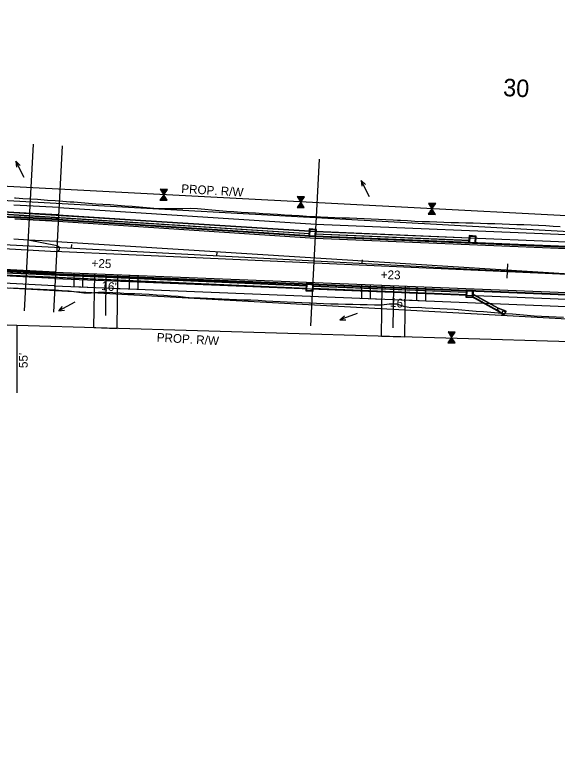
# Model space of a CAD drawing. Extents: x 670017 to 673226, y 705371 to 707498.
# Drawn here: x 672160 to 672533, y 706170 to 706677 of the extents above; entities that cross this region are included whole.
import ezdxf

# ---------------------------------------------------------------- set-up
doc = ezdxf.new("R2010")
doc.units = 0
for name, color, linetype in [('EL L 264', 7, 'Continuous'), ('EL R 264', 7, 'Continuous'), ('R_Drainage Flow Lines', 7, 'Continuous'), ('R_Drainage Stage 1', 7, 'Continuous'), ('R_Drainage Stage 2', 7, 'Continuous'), ('R_Drainage Stage 2A', 7, 'Continuous'), ('R_Drive Annot Stage 2', 7, 'Continuous'), ('R_Drive Stage 2', 7, 'Continuous'), ('R_Fence', 7, 'Continuous'), ('R_Horz Alg', 7, 'Continuous'), ('R_Horz Alg Station', 7, 'Continuous'), ('R_Horz Alg Station Annot', 7, 'Continuous'), ('R_No Plot', 7, 'Continuous'), ('R_No Plot FOC', 7, 'Continuous'), ('R_Proposed Const Limits', 7, 'Continuous'), ('R_Proposed Const Limits Stage 2', 7, 'Continuous'), ('R_Proposed Median', 7, 'Continuous'), ('R_Proposed Road', 7, 'Continuous'), ('R_Proposed Road Stage 2', 7, 'Continuous'), ('R_Proposed Sidewalk Stage 1', 7, 'Continuous'), ('R_Proposed Sidewalk Stage 2', 7, 'Continuous'), ('R_ROW', 7, 'Continuous'), ('R_ROW Annot', 7, 'Continuous'), ('R_Striping', 7, 'Continuous'), ('R_Water Annot', 7, 'Continuous'), ('S_EXIST_ROW', 7, 'Continuous')]:
    doc.layers.add(name, color=color, linetype=linetype)

# ---------------------------------------------------------------- blocks, each defined once
blk = doc.blocks.new('FLOW ARROW')
at = {"layer": 'R_Water Annot'}
for p, q in [((-12.57, 0), (0, 0)), ((0, 0), (-3.85, 1.4)), ((0, 0), (-3.85, -1.4))]:
    blk.add_line(p, q, dxfattribs=at)

msp = doc.modelspace()

# ---------------------------------------------------------------- linework, layer by layer
at = {"layer": 'EL L 264'}
for p, q in [((672160.34, 706537.01), (672189.95, 706535.46)), ((672160.34, 706537.01), (672189.95, 706535.46)), ((672189.95, 706535.46), (672366.78, 706523.88)), ((672189.95, 706535.46), (672366.78, 706523.88)), ((672366.78, 706523.88), (672574.61, 706515.27)), ((672366.78, 706523.88), (672574.61, 706515.27))]:
    msp.add_line(p, q, dxfattribs=at)
at = {"layer": 'EL R 264'}
for p, q in [((671935.55, 706513.76), (672188.31, 706500.5)), ((672187.89, 706500.52), (672563.37, 706485.4))]:
    msp.add_line(p, q, dxfattribs=at)
at = {"layer": 'R_Drainage Stage 1'}
for p, q in [((672362.93, 706526.71), (672152.34, 706540.08)), ((672362.94, 706526.88), (672152.35, 706540.24)), ((672363.02, 706528.38), (672152.43, 706541.74)), ((672363.03, 706528.54), (672152.44, 706541.91)), ((672472.91, 706523.74), (672367.01, 706528.17)), ((672472.92, 706523.9), (672367.02, 706528.33)), ((672472.84, 706522.24), (672366.93, 706526.67)), ((672472.83, 706522.07), (672366.93, 706526.5))]:
    msp.add_line(p, q, dxfattribs=at)
for points in [[(672367.34, 706524.88), (672367.6, 706529.87), (672362.61, 706530.13), (672362.35, 706525.14)], [(672366.87, 706525.4), (672367.08, 706529.4), (672363.08, 706529.6), (672362.87, 706525.61)], [(672477.24, 706520.28), (672477.5, 706525.27), (672472.51, 706525.53), (672472.25, 706520.54)], [(672476.77, 706520.8), (672476.98, 706524.8), (672472.98, 706525.01), (672472.77, 706521.01)]]:
    msp.add_lwpolyline(points, close=True, dxfattribs=at)
at = {"layer": 'R_Drainage Stage 2'}
for p, q in [((672360.96, 706489.14), (672125.16, 706499.41)), ((672360.97, 706489.3), (672125.17, 706499.57)), ((672361.05, 706490.8), (672125.25, 706501.07)), ((672361.05, 706490.97), (672125.26, 706501.24)), ((672470.88, 706484.87), (672364.96, 706489.13)), ((672470.88, 706484.7), (672364.96, 706488.97)), ((672470.95, 706486.37), (672365.04, 706490.63)), ((672470.95, 706486.53), (672365.05, 706490.8)), ((672474.79, 706483.46), (672491.71, 706474.13)), ((672491.79, 706474.27), (672474.83, 706483.62)), ((672474.9, 706485.3), (672492.51, 706475.59)), ((672492.59, 706475.73), (672474.91, 706485.48))]:
    msp.add_line(p, q, dxfattribs=at)
for points in [[(672360.64, 706492.59), (672360.38, 706487.6), (672365.37, 706487.34), (672365.63, 706492.33)], [(672361.11, 706492.07), (672360.9, 706488.07), (672364.9, 706487.86), (672365.11, 706491.86)], [(672470.31, 706483.14), (672475.31, 706482.94), (672475.52, 706487.93), (672470.52, 706488.14)], [(672470.83, 706483.62), (672474.83, 706483.46), (672474.99, 706487.45), (672471, 706487.62)]]:
    msp.add_lwpolyline(points, close=True, dxfattribs=at)
at = {"layer": 'R_Drainage Stage 2A'}
for p, q in [((672491.71, 706474.13), (672491.81, 706474.31)), ((672496.46, 706470.69), (672491.71, 706474.13)), ((672491.81, 706474.31), (672492.5, 706475.56)), ((672491.81, 706474.31), (672492.01, 706474.19)), ((672492.01, 706474.19), (672492.71, 706475.45)), ((672496.55, 706470.87), (672492.02, 706474.21)), ((672492.5, 706475.56), (672492.59, 706475.74)), ((672492.5, 706475.56), (672492.71, 706475.45)), ((672498.04, 706473.56), (672492.59, 706475.74)), ((672497.94, 706473.38), (672492.7, 706475.43)), ((672496.55, 706470.87), (672495.49, 706472.07)), ((672495.49, 706472.07), (672496.46, 706470.69)), ((672497.94, 706473.38), (672496.36, 706473.65)), ((672496.36, 706473.65), (672498.04, 706473.56)), ((672496.55, 706470.87), (672497.94, 706473.38)), ((672497.94, 706473.38), (672498.04, 706473.56)), ((672496.55, 706470.87), (672496.46, 706470.69))]:
    msp.add_line(p, q, dxfattribs=at)
msp.add_arc((672496.2, 706472.7), 0.957, 80.5096, 221.7347, dxfattribs=at)
at = {"layer": 'R_Drive Stage 2'}
for p, q in [((672201.14, 706490.48), (672201.27, 706499.98)), ((672207.14, 706490.22), (672207.27, 706499.74)), ((672214.76, 706462.29), (672215.26, 706498.99)), ((672230.75, 706461.81), (672231.25, 706498.77)), ((672239.12, 706489.05), (672239.25, 706498.45)), ((672245.12, 706488.71), (672245.25, 706498.21)), ((672398.78, 706482.52), (672398.9, 706491.8)), ((672404.77, 706482.28), (672404.9, 706491.58)), ((672201.14, 706490.48), (672215.13, 706489.91)), ((672231.13, 706489.27), (672245.12, 706488.71)), ((672412.42, 706456.46), (672412.9, 706491.29)), ((672428.42, 706455.99), (672428.89, 706490.71)), ((672436.76, 706480.99), (672436.89, 706490.42)), ((672442.76, 706480.75), (672442.89, 706490.2)), ((672398.78, 706482.52), (672412.77, 706481.95)), ((672428.76, 706481.31), (672442.76, 706480.75)), ((672214.76, 706462.29), (672230.75, 706461.81)), ((672412.42, 706456.46), (672428.42, 706455.99))]:
    msp.add_line(p, q, dxfattribs=at)
at = {"layer": 'R_Fence'}
for p, q in [((672260.8, 706557.48), (672260.53, 706557.22)), ((672261.51, 706557.46), (672260.8, 706556.79)), ((672262.21, 706557.43), (672261.07, 706556.36)), ((672262.92, 706557.41), (672261.34, 706555.92)), ((672263.63, 706557.39), (672261.61, 706555.49)), ((672264.33, 706557.37), (672261.88, 706555.06)), ((672263.23, 706552.9), (672260.15, 706549.99)), ((672263.5, 706552.46), (672260.86, 706549.97)), ((672262.96, 706553.33), (672261.59, 706552.04)), ((672265.04, 706557.35), (672262.15, 706554.63)), ((672264.54, 706556.19), (672262.42, 706554.19)), ((672263.07, 706554.12), (672262.69, 706553.76)), ((672354.96, 706552.44), (672354.69, 706552.18)), ((672355.67, 706552.42), (672354.96, 706551.75)), ((672356.38, 706552.4), (672355.23, 706551.32)), ((672357.08, 706552.38), (672355.5, 706550.89)), ((672357.79, 706552.36), (672355.77, 706550.45)), ((672358.5, 706552.34), (672356.04, 706550.02)), ((672359.2, 706552.31), (672356.31, 706549.59)), ((672263.77, 706552.03), (672261.56, 706549.95)), ((672264.04, 706551.6), (672262.27, 706549.93)), ((672264.31, 706551.17), (672262.98, 706549.91)), ((672264.58, 706550.73), (672263.68, 706549.89)), ((672264.85, 706550.3), (672264.39, 706549.87)), ((672265.12, 706549.87), (672265.1, 706549.85)), ((672357.39, 706547.86), (672354.31, 706544.96)), ((672357.66, 706547.43), (672355.02, 706544.94)), ((672357.12, 706548.29), (672355.75, 706547)), ((672358.71, 706551.16), (672356.58, 706549.16)), ((672357.23, 706549.08), (672356.85, 706548.72)), ((672445.08, 706547.71), (672444.81, 706547.45)), ((672445.78, 706547.69), (672445.08, 706547.02)), ((672446.49, 706547.67), (672445.35, 706546.59)), ((672447.2, 706547.65), (672445.62, 706546.16)), ((672447.91, 706547.63), (672445.89, 706545.72)), ((672448.61, 706547.61), (672446.16, 706545.29)), ((672449.32, 706547.59), (672446.43, 706544.86)), ((672357.93, 706546.99), (672355.73, 706544.91)), ((672358.2, 706546.56), (672356.43, 706544.89)), ((672358.47, 706546.13), (672357.14, 706544.87)), ((672358.74, 706545.7), (672357.85, 706544.85)), ((672359.01, 706545.26), (672358.55, 706544.83)), ((672359.28, 706544.83), (672359.26, 706544.81)), ((672447.51, 706543.13), (672444.43, 706540.23)), ((672447.78, 706542.7), (672445.13, 706540.21)), ((672448.05, 706542.26), (672445.84, 706540.18)), ((672447.24, 706543.56), (672445.87, 706542.27)), ((672448.82, 706546.43), (672446.7, 706544.43)), ((672447.34, 706544.35), (672446.97, 706543.99)), ((672448.32, 706541.83), (672446.55, 706540.16)), ((672448.59, 706541.4), (672447.25, 706540.14)), ((672448.86, 706540.97), (672447.96, 706540.12)), ((672449.13, 706540.54), (672448.67, 706540.1)), ((672449.4, 706540.1), (672449.37, 706540.08)), ((672458.56, 706459.42), (672458.28, 706459.16)), ((672459.26, 706459.39), (672458.55, 706458.73)), ((672459.97, 706459.37), (672458.82, 706458.29)), ((672460.68, 706459.35), (672459.09, 706457.86)), ((672461.38, 706459.33), (672459.36, 706457.43)), ((672462.09, 706459.31), (672459.63, 706457)), ((672462.8, 706459.29), (672459.9, 706456.56)), ((672462.3, 706458.13), (672460.17, 706456.13)), ((672460.82, 706456.06), (672460.44, 706455.7)), ((672460.98, 706454.83), (672457.9, 706451.93)), ((672461.25, 706454.4), (672458.61, 706451.91)), ((672461.52, 706453.97), (672459.32, 706451.89)), ((672460.71, 706455.27), (672459.34, 706453.98)), ((672461.8, 706453.54), (672460.02, 706451.87)), ((672462.07, 706453.1), (672460.73, 706451.85)), ((672462.34, 706452.67), (672461.44, 706451.83)), ((672462.61, 706452.24), (672462.14, 706451.81)), ((672462.88, 706451.81), (672462.85, 706451.78))]:
    msp.add_line(p, q, dxfattribs=at)
for points in [[(672262.75, 706553.66), (672262.75, 706553.68), (672265.36, 706557.34), (672260.36, 706557.49), (672262.74, 706553.67), (672262.74, 706553.66), (672260.14, 706549.99), (672265.14, 706549.84), (672262.75, 706553.66)], [(672356.92, 706548.62), (672356.92, 706548.64), (672359.52, 706552.31), (672354.52, 706552.45), (672356.91, 706548.64), (672356.91, 706548.62), (672354.3, 706544.96), (672359.3, 706544.81), (672356.92, 706548.62)], [(672447.03, 706543.89), (672447.03, 706543.91), (672449.64, 706547.58), (672444.64, 706547.72), (672447.02, 706543.91), (672447.02, 706543.9), (672444.42, 706540.23), (672449.41, 706540.08), (672447.03, 706543.89)], [(672460.51, 706455.6), (672460.51, 706455.61), (672463.11, 706459.28), (672458.12, 706459.43), (672460.5, 706455.61), (672460.5, 706455.6), (672457.89, 706451.93), (672462.89, 706451.78), (672460.51, 706455.6)]]:
    msp.add_lwpolyline(points, dxfattribs=at)
at = {"layer": 'R_Horz Alg'}
msp.add_line((670501.52, 706606.05), (672734.79, 706488.84), dxfattribs=at)
at = {"layer": 'R_Horz Alg Station'}
for points in [[(672199.31, 706519.45), (672199.18, 706516.95)], [(672299.18, 706514.2), (672299.05, 706511.71)], [(672399.04, 706508.96), (672398.91, 706506.47)], [(672499.03, 706506.22), (672498.51, 706496.23)]]:
    msp.add_lwpolyline(points, dxfattribs=at)
at = {"layer": 'R_No Plot'}
for p, q in [((672172.89, 706588.43), (672166.88, 706473.92)), ((672192.87, 706587.39), (672186.86, 706472.88)), ((672369.62, 706578.11), (672363.61, 706463.6)), ((672222.87, 706470.74), (672223.26, 706498.88)), ((672420.5, 706462.2), (672420.89, 706490.82))]:
    msp.add_line(p, q, dxfattribs=at)
msp.add_lwpolyline([(672600.73, 706535.93), (672600.73, 706535.93), (672146.36, 706559.78), (671852.81, 706595.21), (671791.92, 706679.49), (671797.39, 707089.58)], dxfattribs=at)
at = {"layer": 'R_No Plot FOC'}
for p, q in [((672190.01, 706536.46), (672160.39, 706538.01)), ((672190.01, 706536.46), (672366.83, 706524.88)), ((672366.83, 706524.88), (672574.65, 706516.27)), ((672187.85, 706499.52), (671935.5, 706512.76)), ((672187.85, 706499.52), (672563.33, 706484.4))]:
    msp.add_line(p, q, dxfattribs=at)
msp.add_arc((672194.98, 707197.1), 660, 260.94679, 266.99576, dxfattribs=at)
at = {"layer": 'R_Proposed Const Limits'}
msp.add_lwpolyline([(672160.07, 706551.56), (672160.95, 706551.5), (672165.93, 706551.17), (672170.92, 706550.85), (672175.91, 706550.52), (672182.94, 706550.01), (672188.04, 706549.67), (672193.32, 706549.28), (672198.4, 706548.87), (672201.03, 706548.72), (672206.02, 706548.33), (672211, 706547.92), (672215.99, 706547.52), (672220.97, 706547.16), (672225.97, 706546.88), (672230.95, 706546.49), (672235.94, 706546.09), (672240.92, 706545.7), (672245.91, 706545.3), (672250.89, 706544.9), (672255.88, 706544.49), (672260.86, 706544.11), (672265.88, 706544.17), (672270.89, 706544.12), (672275.9, 706544.22), (672280.92, 706544.32), (672285.92, 706544.11), (672290.9, 706543.68), (672295.88, 706543.22), (672300.87, 706542.77), (672305.85, 706542.37), (672310.84, 706542.07), (672315.83, 706541.77), (672320.82, 706541.47), (672325.82, 706541.16), (672330.81, 706540.86), (672335.8, 706540.55), (672340.79, 706540.24), (672345.78, 706539.94), (672350.77, 706539.64), (672355.76, 706539.34), (672360.75, 706539.04), (672365.74, 706538.72), (672366.74, 706538.65), (672370.38, 706538.48), (672375.38, 706538.25), (672380.38, 706538.03), (672385.37, 706537.87), (672390.37, 706537.72), (672395.37, 706537.56), (672400.37, 706537.4), (672405.36, 706537.15), (672410.36, 706536.89), (672415.35, 706536.63), (672420.34, 706536.37), (672423.34, 706536.22), (672425.34, 706536.11), (672430.33, 706535.86), (672435.33, 706535.59), (672440.32, 706535.34), (672445.32, 706535.17), (672450.31, 706535), (672455.31, 706534.83), (672460.31, 706534.68), (672465.31, 706534.59), (672470.31, 706534.44), (672475.31, 706534.28), (672480.31, 706534.12), (672485.3, 706533.96), (672490.3, 706533.8), (672495.3, 706533.64), (672500.3, 706533.47), (672505.29, 706533.29), (672510.29, 706533.11), (672515.29, 706533), (672520.28, 706532.72), (672525.28, 706532.42), (672530.27, 706532.12), (672535.26, 706531.81)], dxfattribs=at)
at = {"layer": 'R_Proposed Const Limits Stage 2'}
msp.add_lwpolyline([(672157.7, 706489.66), (672162.69, 706489.42), (672167.69, 706489.2), (672172.68, 706488.97), (672177.68, 706488.75), (672182.67, 706488.51), (672187.81, 706488.2), (672192.8, 706487.93), (672197.79, 706487.55), (672202.77, 706486.93), (672207.75, 706486.27), (672212.75, 706486.23), (672217.78, 706486.71), (672222.78, 706486.63), (672227.78, 706486.43), (672232.78, 706486.33), (672237.76, 706485.86), (672242.76, 706485.83), (672247.76, 706485.62), (672252.75, 706485.26), (672257.74, 706484.9), (672262.73, 706484.55), (672267.72, 706484.2), (672272.71, 706483.84), (672277.69, 706483.29), (672282.68, 706482.73), (672287.68, 706482.75), (672292.68, 706482.54), (672297.67, 706482.33), (672302.67, 706482.12), (672307.66, 706481.92), (672312.66, 706481.71), (672317.66, 706481.51), (672322.65, 706481.31), (672327.65, 706481.11), (672332.64, 706480.79), (672337.64, 706480.55), (672342.63, 706480.3), (672347.63, 706480.06), (672352.62, 706479.82), (672357.61, 706479.57), (672362.61, 706479.34), (672363.61, 706479.29), (672367.6, 706479.1), (672372.6, 706478.86), (672377.6, 706478.66), (672382.6, 706478.55), (672387.6, 706478.45), (672392.6, 706478.35), (672397.6, 706478.26), (672402.6, 706478.17), (672407.6, 706478.07), (672412.6, 706477.98), (672417.63, 706478.73), (672420.64, 706478.73), (672422.63, 706478.6), (672427.58, 706477.07), (672432.55, 706476.25), (672437.55, 706476.33), (672442.54, 706475.88), (672447.54, 706475.72), (672452.54, 706475.56), (672457.53, 706475.32), (672462.52, 706475.04), (672467.51, 706474.56), (672472.5, 706474.08), (672477.48, 706473.72), (672482.47, 706473.34), (672487.46, 706472.93), (672492.45, 706472.51), (672497.44, 706472.1), (672502.43, 706471.69), (672507.41, 706471.28), (672512.4, 706470.88), (672517.39, 706470.45), (672522.38, 706470.13), (672527.38, 706469.91), (672532.37, 706469.7), (672537.37, 706469.49)], dxfattribs=at)
at = {"layer": 'R_Proposed Median'}
for p, q in [((672189.04, 706514.48), (671906.9, 706529.28)), ((672169.47, 706522.51), (672159.6, 706523.03)), ((672189.54, 706518.43), (672169.47, 706522.51))]:
    msp.add_line(p, q, dxfattribs=at)
msp.add_arc((672189.15, 706516.47), 2, 266.9958, 78.465, dxfattribs=at)
at = {"layer": 'R_Proposed Road'}
for p, q in [((672190.04, 706536.96), (672160.42, 706538.51)), ((672189.95, 706535.46), (672160.34, 706537.01)), ((672189.95, 706535.46), (672366.78, 706523.88)), ((672190.04, 706536.96), (672366.86, 706525.38)), ((672366.78, 706523.88), (672574.61, 706515.27)), ((672366.86, 706525.38), (672574.67, 706516.77))]:
    msp.add_line(p, q, dxfattribs=at)
msp.add_arc((672194.98, 707197.1), 659.5, 260.94679, 266.99576, dxfattribs=at)
at = {"layer": 'R_Proposed Road Stage 2'}
for p, q in [((672188.23, 706499), (671935.47, 706512.26)), ((672188.31, 706500.5), (671935.55, 706513.76)), ((672187.83, 706499.02), (672563.31, 706483.9)), ((672187.89, 706500.52), (672563.37, 706485.4))]:
    msp.add_line(p, q, dxfattribs=at)
at = {"layer": 'R_Proposed Sidewalk Stage 1'}
for p, q in [((672190.51, 706544.94), (672159.78, 706546.55)), ((672190.51, 706544.94), (672367.33, 706533.36)), ((672190.21, 706539.95), (672159.52, 706541.56)), ((672190.21, 706539.95), (672367.04, 706528.37)), ((672367.19, 706533.37), (672575, 706524.76)), ((672366.98, 706528.37), (672574.8, 706519.77))]:
    msp.add_line(p, q, dxfattribs=at)
at = {"layer": 'R_Proposed Sidewalk Stage 2'}
for p, q in [((672187.68, 706496.02), (671935.32, 706509.27)), ((672187.45, 706491.03), (671935.05, 706504.27)), ((672187.68, 706496.02), (672571.31, 706480.57)), ((672187.45, 706491.03), (672572.53, 706475.52))]:
    msp.add_line(p, q, dxfattribs=at)
at = {"layer": 'R_ROW'}
for points in [[(672600.73, 706535.93), (672600.73, 706535.93), (672146.36, 706559.78), (671852.81, 706595.21), (671791.92, 706679.49), (671797.39, 707089.58)], [(672596.28, 706451.05), (672596.28, 706451.05), (672161.7, 706463.84), (671891.46, 706473.02), (671825.24, 706451.46), (671776.29, 706399.8), (671754.1, 706085.43), (671832.11, 706032.37), (671817.47, 705912.84), (671726.19, 705881.35)]]:
    msp.add_lwpolyline(points, dxfattribs=at)
at = {"layer": 'R_ROW Annot'}
msp.add_lwpolyline([(672161.7, 706463.84), (672161.7, 706448.84), (672161.7, 706417.47)], dxfattribs=at)
at = {"layer": 'R_Striping'}
for p, q in [((672189.02, 706521.63), (672169.47, 706522.51)), ((672189.02, 706521.63), (672573.67, 706497.3)), ((672573.67, 706497.3), (672187.71, 706514.55))]:
    msp.add_line(p, q, dxfattribs=at)
at = {"layer": 'S_EXIST_ROW'}
for points in [[(670020.59, 706668.53), (670619.99, 706639.58), (670619.86, 706634.58), (671728.16, 706573.3), (673225.88, 706490.48)], [(670017.21, 706598.61), (670616.41, 706569.67), (670616.54, 706574.67), (671724.85, 706513.39), (673222.56, 706430.57)]]:
    msp.add_lwpolyline(points, dxfattribs=at)

# ---------------------------------------------------------------- block references
at = {"layer": 'R_Drainage Flow Lines'}
for p, rotation in [((672161, 706576.64), 117.15978551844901), ((672398.41, 706563.52), 117.15978551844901), ((672190.54, 706473.8), -151.36016280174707), ((672383.77, 706467.7), -160.1943447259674)]:
    msp.add_blockref('FLOW ARROW', p, dxfattribs=dict(at, rotation=rotation))

# ---------------------------------------------------------------- texts
at = {"layer": 'R_Drive Annot Stage 2'}
for s, rotation, p in [('+25', 357.5674, (672213.01, 706503.74)), ('+23', 358.8755, (672411.8, 706495.74)), ("16'", 353.9972, (672219.61, 706488.25)), ("16'", 353.9972, (672418.03, 706476.89))]:
    msp.add_text(s, height=6, rotation=rotation, dxfattribs=at).set_placement(p)
at = {"layer": 'R_Horz Alg Station Annot'}
msp.add_text('30', height=12, rotation=356.9958, dxfattribs=at).set_placement((672495.76, 706621.55))
at = {"layer": 'R_ROW Annot'}
for s, rotation, p in [('PROP. R/W', 356.6321, (672274.63, 706554.89)), ('PROP. R/W', 356.6321, (672257.76, 706452.7)), ("55'", 90, (672169.2, 706434.51))]:
    msp.add_text(s, height=6, rotation=rotation, dxfattribs=at).set_placement(p)

doc.saveas('drawing.dxf')
